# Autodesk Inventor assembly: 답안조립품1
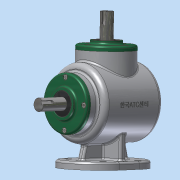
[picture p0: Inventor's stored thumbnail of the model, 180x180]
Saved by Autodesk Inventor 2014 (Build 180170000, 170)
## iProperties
Created: 2023-01
Part Number: 답안조립품1
Document SubType Name: Assembly
Designer: dg
Author: dg
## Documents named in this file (14)
- C:\Users\dg\Desktop\새 폴더\답안조립품1.iam
- C:\Users\dg\Desktop\새 폴더\본체.ipt
- C:\Users\dg\Desktop\새 폴더\메인 베벨기어.ipt
- C:\Users\dg\Desktop\새 폴더\메인 축.ipt
- 메인 축.ipt
- C:\Users\dg\Desktop\새 폴더\서브 베벨기어.ipt
- C:\Users\dg\Desktop\새 폴더\서브 축.ipt
- 서브 축.ipt
- C:\Users\dg\Desktop\새 폴더\키 4x4.ipt
- C:\Users\dg\Desktop\새 폴더\키 5x5.ipt
- C:\Users\dg\Desktop\새 폴더\베어링 6203.ipt
- C:\Users\dg\Desktop\새 폴더\커버.ipt
- C:\Users\dg\Desktop\새 폴더\오일실 17 32 8.ipt
- C:\Users\dg\Desktop\새 폴더\M4.ipt
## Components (8 placed, 1 different names)
1. M4:1
2. M4:3
3. M4:4
4. M4:5
5. M4:2
6. M4:6
7. M4:7
8. M4:8
